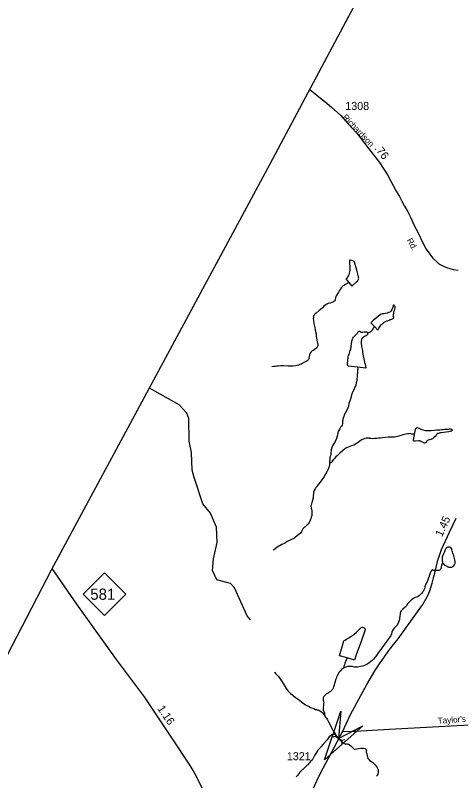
# Model space of a CAD drawing. Extents: x 2220236 to 2384410, y 720751 to 894131.
# Drawn here: x 2254848 to 2261721, y 820039 to 831987 of the extents above; entities that cross this region are included whole.
import ezdxf

# ---------------------------------------------------------------- set-up
doc = ezdxf.new("R2010")
doc.units = 0
doc.layers.add('Default', color=7, linetype='Continuous')

msp = doc.modelspace()

# ---------------------------------------------------------------- linework, layer by layer
at = {"layer": 'Default'}
for p, q in [((2259793, 820724), (2259843, 820734)), ((2259835, 820784), (2259843, 820734)), ((2259843, 820734), (2259942, 820665)), ((2259992, 820676), (2259942, 820665)), ((2259950, 820615), (2259942, 820665))]:
    msp.add_line(p, q, dxfattribs=at)
for points in [[(2293118, 894131), (2291904, 891776), (2258822, 829665), (2255410, 823324), (2242089, 797599), (2231460, 775981), (2225011, 762953), (2220576, 753519)], [(2259442, 830829), (2259637, 830672), (2259678, 830641), (2259785, 830553), (2259927, 830424), (2260043, 830295), (2260179, 830148), (2260368, 829905), (2260533, 829691), (2260655, 829497), (2260791, 829240), (2260842, 829159), (2260882, 829087), (2260922, 829010), (2260967, 828929), (2261022, 828823), (2261066, 828716), (2261133, 828590), (2261201, 828445), (2261262, 828334), (2261317, 828258), (2261359, 828201), (2261449, 828118), (2261481, 828097), (2261522, 828074), (2261576, 828052), (2261683, 828019), (2261762, 828006)], [(2260054, 827816), (2260102, 827761), (2260172, 827825), (2260186, 827837), (2260194, 827847), (2260199, 827856), (2260203, 827865), (2260205, 827872), (2260207, 827882), (2260206, 827895), (2260205, 827906), (2260176, 828007), (2260143, 828133), (2260137, 828143), (2260127, 828151), (2260117, 828155), (2260105, 828159), (2260075, 828164), (2260066, 828164), (2260065, 828156), (2260065, 828120), (2260068, 828060), (2260070, 828026), (2260069, 828004), (2260066, 827986), (2260061, 827955), (2260053, 827934), (2260031, 827898), (2260015, 827880), (2260005, 827872), (2260054, 827816)], [(2260054, 827816), (2260012, 827792), (2259999, 827784), (2259973, 827767), (2259958, 827757), (2259953, 827753), (2259943, 827743), (2259934, 827732), (2259917, 827709), (2259903, 827687), (2259891, 827664), (2259882, 827651), (2259856, 827610), (2259850, 827595), (2259846, 827578), (2259840, 827543), (2259838, 827536), (2259834, 827532), (2259825, 827524), (2259816, 827517), (2259802, 827511), (2259789, 827504), (2259761, 827493), (2259731, 827486), (2259709, 827477), (2259694, 827468), (2259681, 827459), (2259660, 827439), (2259642, 827420), (2259606, 827388), (2259592, 827378), (2259545, 827339), (2259527, 827325), (2259517, 827315), (2259511, 827307), (2259506, 827300), (2259503, 827294), (2259502, 827285), (2259500, 827273), (2259499, 827251), (2259501, 827236), (2259503, 827219), (2259508, 827177), (2259512, 827153), (2259521, 827114), (2259529, 827073), (2259542, 827017), (2259546, 826980), (2259550, 826947), (2259554, 826922), (2259561, 826891), (2259565, 826870), (2259567, 826856), (2259567, 826844), (2259567, 826830), (2259563, 826816), (2259558, 826804), (2259553, 826797), (2259533, 826778), (2259512, 826763), (2259497, 826755), (2259482, 826747), (2259467, 826736), (2259458, 826727), (2259448, 826713), (2259443, 826699), (2259440, 826690), (2259437, 826677), (2259435, 826664), (2259427, 826627), (2259422, 826615), (2259417, 826607), (2259411, 826601), (2259396, 826588), (2259363, 826570), (2259326, 826552), (2259266, 826525), (2259225, 826514), (2259180, 826508), (2259158, 826508), (2259142, 826508), (2259104, 826510), (2259036, 826513), (2258990, 826513), (2258954, 826508), (2258923, 826508), (2258901, 826507), (2258877, 826505), (2258853, 826499), (2258849, 826499)], [(2260460, 827122), (2260505, 827074), (2260521, 827104), (2260530, 827118), (2260542, 827133), (2260558, 827153), (2260566, 827161), (2260571, 827169), (2260579, 827177), (2260595, 827189), (2260605, 827195), (2260645, 827216), (2260655, 827220), (2260683, 827230), (2260699, 827236), (2260710, 827239), (2260726, 827245), (2260733, 827249), (2260744, 827255), (2260750, 827263), (2260753, 827267), (2260753, 827273), (2260750, 827278), (2260748, 827291), (2260748, 827300), (2260748, 827313), (2260753, 827338), (2260758, 827359), (2260762, 827371), (2260766, 827381), (2260773, 827403), (2260775, 827417), (2260777, 827429), (2260775, 827441), (2260773, 827448), (2260767, 827454), (2260759, 827460), (2260756, 827462), (2260751, 827460), (2260747, 827455), (2260744, 827447), (2260739, 827429), (2260729, 827406), (2260722, 827390), (2260708, 827371), (2260692, 827354), (2260672, 827346), (2260654, 827339), (2260624, 827330), (2260597, 827326), (2260578, 827325), (2260560, 827321), (2260540, 827311), (2260513, 827287), (2260439, 827229), (2260406, 827197), (2260398, 827189), (2260460, 827122)], [(2260460, 827122), (2260449, 827118), (2260440, 827112), (2260436, 827108), (2260432, 827102), (2260429, 827096), (2260426, 827089), (2260424, 827086), (2260421, 827078), (2260412, 827066), (2260408, 827061), (2260403, 827055), (2260393, 827047), (2260384, 827041), (2260373, 827035), (2260359, 827031), (2260349, 827030), (2260340, 827032)], [(2260188, 826493), (2260048, 826508), (2260039, 826517), (2260034, 826528), (2260032, 826552), (2260031, 826560), (2260036, 826590), (2260039, 826618), (2260041, 826636), (2260045, 826656), (2260050, 826676), (2260056, 826692), (2260066, 826715), (2260076, 826752), (2260082, 826772), (2260083, 826782), (2260085, 826795), (2260089, 826811), (2260097, 826858), (2260101, 826888), (2260104, 826915), (2260110, 826935), (2260118, 826949), (2260126, 826961), (2260136, 826971), (2260181, 827021), (2260195, 827042), (2260199, 827045), (2260202, 827050), (2260206, 827053), (2260209, 827053), (2260217, 827056), (2260221, 827056), (2260227, 827054), (2260231, 827050), (2260233, 827048), (2260242, 827043), (2260255, 827040), (2260259, 827040), (2260273, 827042), (2260290, 827045), (2260303, 827047), (2260312, 827046), (2260322, 827046), (2260329, 827044), (2260335, 827041), (2260339, 827034), (2260340, 827032)], [(2260340, 827032), (2260341, 827031), (2260343, 827024), (2260343, 827021), (2260343, 827013), (2260342, 827006), (2260339, 827001), (2260331, 826990), (2260316, 826981), (2260296, 826971), (2260283, 826964), (2260277, 826960), (2260272, 826956), (2260268, 826952), (2260266, 826950), (2260262, 826946), (2260258, 826942), (2260254, 826938), (2260252, 826932), (2260252, 826926), (2260250, 826914), (2260248, 826898), (2260248, 826872), (2260253, 826816), (2260257, 826794), (2260264, 826754), (2260268, 826729), (2260276, 826672), (2260286, 826625), (2260291, 826597), (2260300, 826569), (2260308, 826542), (2260312, 826518), (2260314, 826503), (2260318, 826489), (2260318, 826480), (2260188, 826493)], [(2260188, 826493), (2260192, 826465), (2260190, 826445), (2260189, 826415), (2260187, 826399), (2260183, 826385), (2260181, 826369), (2260181, 826343), (2260179, 826314), (2260176, 826288), (2260170, 826252), (2260161, 826213), (2260135, 826155), (2260104, 826089), (2260094, 826065), (2260088, 826038), (2260083, 826008), (2260069, 825967), (2260055, 825928), (2260046, 825888), (2260036, 825862), (2260020, 825824), (2259995, 825778), (2259987, 825759), (2259983, 825748), (2259973, 825723), (2259965, 825697), (2259960, 825684), (2259958, 825667), (2259956, 825651), (2259954, 825633), (2259952, 825615), (2259952, 825609), (2259948, 825591), (2259940, 825575), (2259931, 825561), (2259913, 825534), (2259901, 825515), (2259887, 825488), (2259880, 825464), (2259876, 825434), (2259872, 825416), (2259860, 825382), (2259839, 825334), (2259815, 825292), (2259797, 825264), (2259788, 825239), (2259780, 825206), (2259778, 825195), (2259774, 825162), (2259772, 825136), (2259765, 825108), (2259759, 825087), (2259757, 825078), (2259755, 825067), (2259755, 825055), (2259754, 825029), (2259754, 825011), (2259754, 824991)], [(2258517, 822552), (2258467, 822612), (2258271, 823049), (2258204, 823116), (2257995, 823173), (2257928, 823322), (2257943, 823505), (2257999, 823757), (2257989, 823996), (2257895, 824215), (2257777, 824361), (2257641, 824771), (2257607, 824887), (2257596, 825162), (2257561, 825337), (2257558, 825694), (2257524, 825777), (2257407, 825908), (2256941, 826169)], [(2261080, 825446), (2261041, 825447), (2261033, 825449), (2261021, 825455), (2261013, 825457), (2261003, 825459), (2260989, 825456), (2260967, 825452), (2260945, 825448), (2260923, 825444), (2260897, 825438), (2260871, 825430), (2260848, 825423), (2260834, 825419), (2260814, 825413), (2260791, 825409), (2260766, 825404), (2260740, 825400), (2260704, 825400), (2260668, 825400), (2260580, 825393), (2260544, 825388), (2260514, 825386), (2260488, 825382), (2260454, 825380), (2260418, 825377), (2260396, 825379), (2260382, 825383), (2260374, 825385), (2260362, 825387), (2260350, 825387), (2260334, 825386), (2260323, 825386), (2260304, 825380), (2260292, 825377), (2260280, 825372), (2260262, 825366), (2260244, 825356), (2260223, 825339), (2260199, 825321), (2260187, 825311), (2260173, 825301), (2260131, 825278), (2260097, 825264), (2260044, 825247), (2260015, 825234), (2259988, 825216), (2259949, 825185), (2259913, 825154), (2259891, 825132), (2259869, 825112), (2259849, 825094), (2259823, 825064), (2259808, 825046), (2259797, 825033), (2259786, 825018), (2259778, 825007), (2259762, 824996), (2259754, 824991)], [(2261080, 825446), (2261100, 825541), (2261102, 825543), (2261108, 825546), (2261112, 825547), (2261120, 825550), (2261128, 825548), (2261138, 825544), (2261148, 825540), (2261156, 825536), (2261164, 825532), (2261172, 825528), (2261180, 825524), (2261195, 825519), (2261207, 825514), (2261229, 825509), (2261249, 825505), (2261268, 825505), (2261337, 825507), (2261390, 825512), (2261422, 825516), (2261442, 825517), (2261476, 825517), (2261502, 825520), (2261528, 825523), (2261544, 825525), (2261552, 825526), (2261572, 825526), (2261598, 825528), (2261608, 825529), (2261625, 825530), (2261636, 825531), (2261647, 825529), (2261652, 825528), (2261657, 825526), (2261662, 825523), (2261666, 825517), (2261666, 825507), (2261663, 825501), (2261658, 825497), (2261652, 825494), (2261634, 825490), (2261612, 825486), (2261573, 825480), (2261493, 825469), (2261477, 825467), (2261461, 825463), (2261453, 825461), (2261441, 825457), (2261429, 825449), (2261423, 825442), (2261417, 825434), (2261399, 825412), (2261382, 825396), (2261370, 825387), (2261358, 825378), (2261344, 825370), (2261334, 825365), (2261312, 825361), (2261292, 825355), (2261280, 825350), (2261276, 825347), (2261272, 825343), (2261264, 825333), (2261262, 825325), (2261260, 825321), (2261256, 825315), (2261254, 825313), (2261248, 825311), (2261236, 825307), (2261230, 825309), (2261216, 825316), (2261202, 825322), (2261182, 825334), (2261176, 825339), (2261166, 825340), (2261154, 825342), (2261140, 825342), (2261086, 825339), (2261072, 825341), (2261064, 825345), (2261060, 825348), (2261080, 825446)], [(2259754, 824991), (2259754, 824989), (2259752, 824970), (2259746, 824945), (2259731, 824901), (2259709, 824863), (2259666, 824788), (2259622, 824722), (2259563, 824645), (2259549, 824629), (2259537, 824615), (2259526, 824595), (2259512, 824567), (2259504, 824541), (2259502, 824529), (2259499, 824481), (2259497, 824455), (2259494, 824437), (2259487, 824412), (2259478, 824381), (2259472, 824361), (2259466, 824341), (2259462, 824331), (2259461, 824326), (2259460, 824323), (2259466, 824292), (2259471, 824277), (2259475, 824251), (2259477, 824226), (2259478, 824207), (2259474, 824179), (2259468, 824153), (2259462, 824133), (2259452, 824107), (2259435, 824072), (2259417, 824048), (2259395, 824024), (2259365, 823997), (2259351, 823987), (2259337, 823971), (2259314, 823927), (2259298, 823905), (2259275, 823884), (2259249, 823860), (2259223, 823841), (2259203, 823826), (2259149, 823800), (2259114, 823784), (2259093, 823771), (2259066, 823753), (2259036, 823737), (2259008, 823726), (2258980, 823712), (2258962, 823702), (2258934, 823686), (2258896, 823654), (2258883, 823643), (2258874, 823637)], [(2259962, 820814), (2260076, 821063), (2260177, 821255), (2260332, 821539), (2260460, 821753), (2260542, 821877), (2260597, 821958), (2260678, 822072), (2260753, 822171), (2260822, 822253), (2261126, 822675), (2261179, 822747), (2261206, 822791), (2261256, 822873), (2261284, 822930), (2261315, 823003), (2261353, 823121), (2261375, 823204), (2261394, 823279), (2261415, 823373), (2261444, 823480), (2261466, 823553), (2261499, 823647), (2261626, 823917), (2261729, 824139)], [(2261525, 823429), (2261542, 823411), (2261574, 823392), (2261582, 823387), (2261590, 823382), (2261598, 823379), (2261606, 823376), (2261612, 823374), (2261618, 823372), (2261624, 823371), (2261632, 823370), (2261638, 823370), (2261652, 823372), (2261659, 823374), (2261672, 823379), (2261684, 823387), (2261692, 823395), (2261702, 823409), (2261708, 823422), (2261711, 823433), (2261713, 823443), (2261711, 823460), (2261705, 823487), (2261690, 823547), (2261676, 823593), (2261671, 823614), (2261668, 823628), (2261663, 823648), (2261661, 823660), (2261657, 823666), (2261647, 823678), (2261639, 823682), (2261628, 823684), (2261617, 823686), (2261608, 823685), (2261599, 823684), (2261585, 823680), (2261575, 823674), (2261569, 823666), (2261558, 823644), (2261544, 823611), (2261532, 823580), (2261516, 823543), (2261512, 823528), (2261512, 823525), (2261512, 823513), (2261511, 823503), (2261511, 823493), (2261511, 823483), (2261512, 823469), (2261514, 823457), (2261517, 823443), (2261519, 823437), (2261525, 823429)], [(2261525, 823429), (2261520, 823427), (2261515, 823425), (2261511, 823423), (2261506, 823418), (2261504, 823415), (2261501, 823409), (2261499, 823403), (2261498, 823395), (2261496, 823381), (2261494, 823367), (2261493, 823358), (2261490, 823351), (2261486, 823343), (2261482, 823337), (2261477, 823331), (2261468, 823325), (2261460, 823323), (2261450, 823321), (2261436, 823319), (2261414, 823318), (2261399, 823318), (2261386, 823320), (2261380, 823322), (2261368, 823328), (2261366, 823329), (2261363, 823329), (2261358, 823329), (2261354, 823327), (2261349, 823324), (2261345, 823319), (2261337, 823307), (2261329, 823292), (2261307, 823232), (2261286, 823173), (2261269, 823133), (2261252, 823095), (2261241, 823063), (2261232, 823034), (2261224, 823015), (2261212, 822994), (2261204, 822983), (2261188, 822963), (2261174, 822948), (2261155, 822930), (2261134, 822914), (2261113, 822903), (2261087, 822897), (2261061, 822883), (2261039, 822869), (2261011, 822844), (2260993, 822824), (2260981, 822812), (2260971, 822798), (2260956, 822774), (2260932, 822750), (2260893, 822713), (2260877, 822698), (2260870, 822690), (2260862, 822674), (2260858, 822665), (2260857, 822659), (2260855, 822641), (2260853, 822631), (2260851, 822615), (2260850, 822605), (2260846, 822572), (2260844, 822555), (2260836, 822527), (2260825, 822499), (2260814, 822481), (2260801, 822462), (2260779, 822441), (2260761, 822422), (2260743, 822400), (2260734, 822383), (2260726, 822356), (2260720, 822334), (2260708, 822308), (2260682, 822269), (2260669, 822248), (2260645, 822217), (2260602, 822153), (2260563, 822103), (2260534, 822062), (2260513, 822036), (2260483, 821996), (2260436, 821935), (2260416, 821915), (2260396, 821901), (2260364, 821873), (2260340, 821856), (2260287, 821833), (2260233, 821820), (2260187, 821813), (2260164, 821811), (2260143, 821813)], [(2258594, 818108), (2258553, 818205), (2258468, 818389), (2258398, 818536), (2258303, 818741), (2258224, 818931), (2258106, 819192), (2257956, 819536), (2257827, 819807), (2257755, 819945), (2257690, 820071), (2257684, 820085), (2257625, 820198), (2257577, 820279), (2257494, 820402), (2257395, 820554), (2256862, 821346), (2256428, 821929), (2256084, 822410), (2255806, 822793), (2255425, 823350)], [(2260025, 821955), (2259910, 821989), (2259975, 822221), (2259979, 822229), (2259989, 822231), (2259995, 822233), (2260015, 822246), (2260055, 822269), (2260092, 822293), (2260115, 822308), (2260132, 822320), (2260172, 822357), (2260193, 822379), (2260209, 822395), (2260223, 822410), (2260230, 822417), (2260237, 822423), (2260242, 822428), (2260248, 822432), (2260254, 822434), (2260261, 822436), (2260269, 822435), (2260276, 822433), (2260284, 822430), (2260291, 822426), (2260299, 822420), (2260305, 822414), (2260309, 822410), (2260310, 822404), (2260310, 822398), (2260308, 822392), (2260251, 822229), (2260216, 822129), (2260173, 822019), (2260140, 821923), (2260025, 821955)], [(2260025, 821955), (2260003, 821901), (2259992, 821869), (2259986, 821849), (2259977, 821821), (2259973, 821807), (2259971, 821798)], [(2259971, 821798), (2259969, 821797), (2259953, 821785), (2259939, 821773), (2259918, 821750), (2259904, 821732), (2259876, 821689), (2259861, 821657), (2259853, 821636), (2259847, 821614), (2259839, 821586), (2259831, 821556), (2259825, 821532), (2259816, 821503), (2259809, 821485), (2259796, 821462), (2259781, 821445), (2259768, 821433), (2259747, 821419), (2259729, 821407), (2259717, 821401), (2259705, 821393), (2259687, 821379), (2259673, 821366), (2259663, 821352), (2259659, 821344), (2259655, 821332), (2259653, 821326), (2259652, 821316), (2259652, 821305), (2259654, 821292), (2259658, 821282), (2259660, 821274), (2259661, 821264), (2259660, 821243), (2259658, 821228), (2259657, 821214), (2259653, 821180), (2259653, 821174), (2259653, 821170), (2259653, 821166), (2259654, 821146), (2259659, 821128), (2259664, 821118), (2259668, 821108), (2259672, 821093), (2259674, 821083), (2259674, 821078), (2259673, 821064), (2259672, 821060)], [(2260143, 821813), (2260123, 821819), (2260111, 821822), (2260101, 821824), (2260087, 821824), (2260037, 821820), (2260007, 821814), (2259979, 821803), (2259971, 821798)], [(2258891, 821733), (2258892, 821731), (2258916, 821707), (2258932, 821692), (2258953, 821667), (2258967, 821648), (2258993, 821614), (2259012, 821580), (2259027, 821557), (2259044, 821533), (2259058, 821507), (2259074, 821479), (2259085, 821465), (2259107, 821439), (2259145, 821402), (2259179, 821374), (2259220, 821340), (2259262, 821311), (2259288, 821291), (2259334, 821255), (2259379, 821226), (2259397, 821215), (2259432, 821195), (2259445, 821188), (2259453, 821184), (2259473, 821176), (2259491, 821171), (2259500, 821167), (2259507, 821165), (2259514, 821160), (2259519, 821157), (2259530, 821150), (2259537, 821149), (2259550, 821149), (2259559, 821147), (2259567, 821146), (2259583, 821139), (2259601, 821131), (2259628, 821112), (2259646, 821092), (2259660, 821078), (2259672, 821060)], [(2259672, 821060), (2259674, 821056), (2259690, 821032), (2259704, 821015), (2259719, 820989), (2259731, 820971), (2259737, 820957), (2259755, 820923), (2259778, 820875), (2259800, 820837), (2259810, 820820), (2259820, 820803), (2259839, 820770), (2259841, 820766)], [(2259962, 820814), (2260057, 820807), (2260690, 820845), (2261934, 820913), (2262186, 820925), (2262489, 820948), (2262808, 820963), (2263454, 821001), (2263713, 821013), (2264053, 821030), (2264252, 821044), (2264439, 821057), (2264535, 821072), (2264597, 821088), (2264650, 821097), (2264708, 821113), (2264779, 821133)], [(2258724, 817770), (2258744, 817942), (2258762, 818074), (2258851, 818417), (2259140, 819134), (2259583, 820103), (2259652, 820235), (2259962, 820814)], [(2259841, 820766), (2259821, 820764), (2259813, 820763), (2259806, 820763), (2259799, 820761), (2259787, 820756), (2259765, 820741), (2259747, 820723), (2259713, 820675), (2259705, 820666), (2259664, 820622), (2259652, 820608), (2259618, 820569), (2259609, 820558), (2259595, 820541), (2259572, 820515), (2259539, 820465), (2259520, 820435), (2259502, 820401), (2259479, 820362), (2259461, 820344), (2259450, 820334), (2259437, 820316), (2259425, 820302), (2259411, 820286), (2259405, 820282), (2259381, 820261), (2259360, 820241), (2259350, 820229), (2259335, 820216), (2259324, 820207), (2259304, 820189), (2259288, 820171), (2259275, 820150), (2259269, 820142), (2259256, 820127), (2259247, 820117), (2259230, 820098)], [(2259841, 820766), (2259850, 820750), (2259879, 820718), (2259893, 820700), (2259931, 820662), (2259943, 820651), (2259959, 820637), (2259969, 820629), (2259983, 820619), (2259994, 820614), (2260004, 820612), (2260018, 820613), (2260029, 820613), (2260039, 820610), (2260050, 820607), (2260066, 820597), (2260085, 820584), (2260096, 820574), (2260104, 820564), (2260110, 820556), (2260127, 820540), (2260135, 820534), (2260142, 820532), (2260151, 820532), (2260174, 820537), (2260210, 820543), (2260238, 820545), (2260281, 820547), (2260304, 820544), (2260313, 820540), (2260321, 820534), (2260324, 820523), (2260327, 820507), (2260326, 820495), (2260325, 820489), (2260325, 820478), (2260327, 820472), (2260333, 820457), (2260343, 820405), (2260352, 820386), (2260378, 820360), (2260412, 820335), (2260430, 820321), (2260446, 820307), (2260462, 820287), (2260479, 820267), (2260491, 820251), (2260501, 820231), (2260505, 820220), (2260509, 820208), (2260512, 820188), (2260510, 820166), (2260505, 820141), (2260498, 820128), (2260493, 820118), (2260487, 820110)]]:
    msp.add_lwpolyline(points, dxfattribs=at)
for points in [[(2255909, 822953), (2256242, 823286), (2256575, 822953), (2256242, 822620)], [(2260272, 820895), (2259671, 820367), (2259927, 821125), (2259893, 820700)]]:
    msp.add_lwpolyline(points, close=True, dxfattribs=at)

# ---------------------------------------------------------------- texts
for s, height, p in [('1308', 125, (2259998, 830510)), ('581', 175, (2256018, 822863)), ('1321', 125, (2259086, 820359))]:
    msp.add_text(s, height=height, dxfattribs=at).set_placement(p)
for s, height, rotation, p in [('Richardson', 95, 313.6612, (2259947, 830388)), ('.76', 125, 308.0786, (2260448, 829906)), ('Rd.', 95, 298.4231, (2260954, 828478)), ('1.45', 125, 65.5988, (2261508, 823837)), ('1.16', 125, 303.9354, (2257060, 821165)), ("Taylor's", 95, 4.2986, (2261444, 820926))]:
    msp.add_text(s, height=height, rotation=rotation, dxfattribs=at).set_placement(p)

doc.saveas('drawing.dxf')
